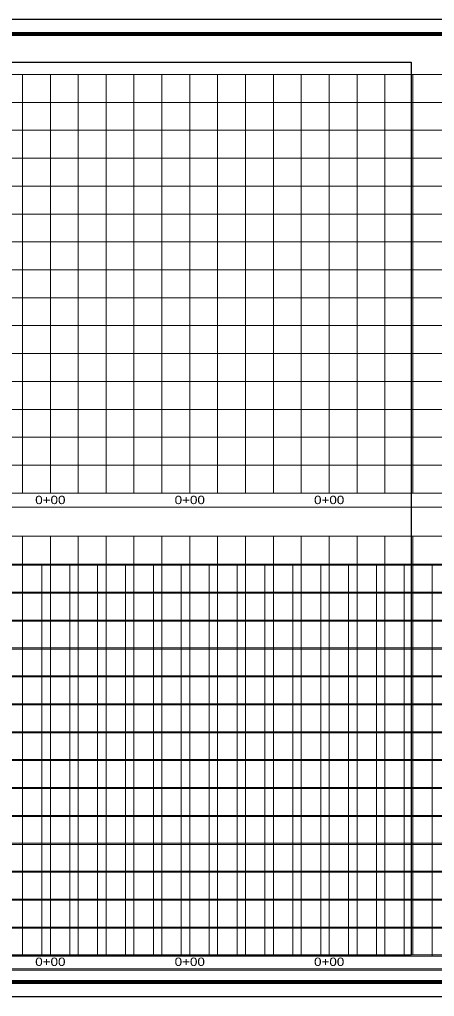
# Model space of a CAD drawing. Extents: x 2246932 to 2264252, y 7095151 to 7098651.
# Drawn here: x 2248981 to 2250469, y 7095151 to 7098651 of the extents above; entities that cross this region are included whole.
import ezdxf
from ezdxf.enums import TextEntityAlignment as Align

# ---------------------------------------------------------------- set-up
doc = ezdxf.new("R2010")
doc.units = 0
doc.header["$LTSCALE"] = 12
for name, color, linetype, lineweight in [('1', 7, 'Continuous', 80), ('59', 7, 'Continuous', 13), ('62', 7, 'Continuous', 13), ('63', 7, 'Continuous', 25)]:
    doc.layers.add(name, color=color, linetype=linetype, lineweight=lineweight)
doc.layers.add('22', color=7, linetype='Continuous')

msp = doc.modelspace()

# ---------------------------------------------------------------- linework, layer by layer
at = {"layer": '1'}
for p, q in [((2264052.09, 7098598.35), (2247157.09, 7098598.35)), ((2247157.09, 7095203.35), (2264052.09, 7095203.35))]:
    msp.add_line(p, q, dxfattribs=at)
at = {"layer": '1', "lineweight": 25}
msp.add_line((2247104.59, 7095150.85), (2264104.59, 7095150.85), dxfattribs=at)
msp.add_lwpolyline([(2264104.59, 7095150.85), (2264104.59, 7098650.85), (2247104.59, 7098650.85), (2247104.59, 7095150.85)], dxfattribs=at)
at = {"layer": '59'}
for p, q in [((2247310.97, 7096695.64), (2262610.97, 7096695.64)), ((2249060.97, 7095295.64), (2249060.97, 7096695.64)), ((2249160.97, 7095295.64), (2249160.97, 7096695.64)), ((2249260.97, 7095295.64), (2249260.97, 7096695.64)), ((2249360.97, 7095295.64), (2249360.97, 7096695.64)), ((2249460.97, 7096695.64), (2249460.97, 7095295.64)), ((2249560.97, 7095295.64), (2249560.97, 7096695.64)), ((2249660.97, 7095295.64), (2249660.97, 7096695.64)), ((2249760.97, 7095295.64), (2249760.97, 7096695.64)), ((2249860.97, 7095295.64), (2249860.97, 7096695.64)), ((2249960.97, 7096695.64), (2249960.97, 7095295.64)), ((2250060.97, 7095295.64), (2250060.97, 7096695.64)), ((2250160.97, 7095295.64), (2250160.97, 7096695.64)), ((2250260.97, 7095295.64), (2250260.97, 7096695.64)), ((2250360.97, 7095295.64), (2250360.97, 7096695.64)), ((2250460.97, 7096695.64), (2250460.97, 7095295.64)), ((2262610.97, 7095295.64), (2247310.97, 7095295.64)), ((2262610.97, 7095245.64), (2247310.97, 7095245.64))]:
    msp.add_line(p, q, dxfattribs=at)
for points in [[(2247460.97, 7096595.64), (2262460.97, 7096595.64), (2262610.97, 7096595.64)], [(2247460.97, 7096495.64), (2262460.97, 7096495.64), (2262610.97, 7096495.64)], [(2247460.97, 7096395.64), (2262460.97, 7096395.64), (2262610.97, 7096395.64)], [(2247460.97, 7096295.64), (2262460.97, 7096295.64), (2262610.97, 7096295.64)], [(2247460.97, 7096195.64), (2262460.97, 7096195.64), (2262610.97, 7096195.64)], [(2247454.92, 7096095.64), (2262460.97, 7096095.64), (2262610.97, 7096095.64)], [(2247460.97, 7095995.64), (2262460.97, 7095995.64), (2262610.97, 7095995.64)], [(2247460.97, 7095895.64), (2262460.97, 7095895.64), (2262610.97, 7095895.64)], [(2247460.97, 7095795.64), (2262460.97, 7095795.64), (2262610.97, 7095795.64)], [(2247460.97, 7095695.64), (2262460.97, 7095695.64), (2262610.97, 7095695.64)], [(2247460.97, 7095595.64), (2262460.97, 7095595.64), (2262610.97, 7095595.64)], [(2247460.97, 7095495.64), (2262460.97, 7095495.64), (2262610.97, 7095495.64)], [(2247460.97, 7095395.64), (2262460.97, 7095395.64), (2262610.97, 7095395.64)]]:
    msp.add_lwpolyline(points, dxfattribs=at)
at = {"layer": '62'}
for p, q in [((2247941.45, 7098454.14), (2263241.45, 7098454.14)), ((2248991.45, 7098454.14), (2248991.45, 7096954.14)), ((2249091.45, 7098454.14), (2249091.45, 7096954.14)), ((2249191.45, 7098454.14), (2249191.45, 7096954.14)), ((2249291.45, 7098454.14), (2249291.45, 7096954.14)), ((2249391.45, 7098454.14), (2249391.45, 7096954.14)), ((2249491.45, 7098454.14), (2249491.45, 7096954.14)), ((2249591.45, 7098454.14), (2249591.45, 7096954.14)), ((2249691.45, 7098454.14), (2249691.45, 7096954.14)), ((2249791.45, 7098454.14), (2249791.45, 7096954.14)), ((2249891.45, 7098454.14), (2249891.45, 7096954.14)), ((2249991.45, 7098454.14), (2249991.45, 7096954.14)), ((2250091.45, 7098454.14), (2250091.45, 7096954.14)), ((2250191.45, 7098454.14), (2250191.45, 7096954.14)), ((2250291.45, 7098454.14), (2250291.45, 7096954.14)), ((2250391.45, 7098454.14), (2250391.45, 7096954.14)), ((2259241.45, 7097654.14), (2249441.45, 7097654.14)), ((2263241.45, 7096954.14), (2247941.45, 7096954.14)), ((2263241.45, 7096904.14), (2247941.45, 7096904.14)), ((2247941.45, 7096799.51), (2263241.45, 7096799.51)), ((2248991.45, 7096799.51), (2248991.45, 7095299.51)), ((2249091.45, 7096799.51), (2249091.45, 7095299.51)), ((2249191.45, 7096799.51), (2249191.45, 7095299.51)), ((2249291.45, 7096799.51), (2249291.45, 7095299.51)), ((2249391.45, 7096799.51), (2249391.45, 7095299.51)), ((2249491.45, 7096799.51), (2249491.45, 7095299.51)), ((2249591.45, 7096799.51), (2249591.45, 7095299.51)), ((2249691.45, 7096799.51), (2249691.45, 7095299.51)), ((2249791.45, 7096799.51), (2249791.45, 7095299.51)), ((2249891.45, 7096799.51), (2249891.45, 7095299.51)), ((2249991.45, 7096799.51), (2249991.45, 7095299.51)), ((2250091.45, 7096799.51), (2250091.45, 7095299.51)), ((2250191.45, 7096799.51), (2250191.45, 7095299.51)), ((2250291.45, 7096799.51), (2250291.45, 7095299.51)), ((2250391.45, 7096799.51), (2250391.45, 7095299.51)), ((2259241.45, 7095999.51), (2249441.45, 7095999.51)), ((2263241.45, 7095299.51), (2247941.45, 7095299.51)), ((2263241.45, 7095249.51), (2247941.45, 7095249.51))]:
    msp.add_line(p, q, dxfattribs=at)
for points in [[(2248091.45, 7098354.14), (2263091.45, 7098354.14), (2263241.45, 7098354.14)], [(2248091.45, 7098254.14), (2263091.45, 7098254.14), (2263241.45, 7098254.14)], [(2248091.45, 7098154.14), (2263091.45, 7098154.14), (2263241.45, 7098154.14)], [(2248091.45, 7098054.14), (2263091.45, 7098054.14), (2263241.45, 7098054.14)], [(2248091.45, 7097954.14), (2263091.45, 7097954.14), (2263241.45, 7097954.14)], [(2248091.45, 7097854.14), (2263091.45, 7097854.14), (2263241.45, 7097854.14)], [(2248091.45, 7097754.14), (2263091.45, 7097754.14), (2263241.45, 7097754.14)], [(2248091.45, 7097654.14), (2263091.45, 7097654.14), (2263241.45, 7097654.14)], [(2248091.45, 7097554.14), (2263091.45, 7097554.14), (2263241.45, 7097554.14)], [(2248091.45, 7097454.14), (2263091.45, 7097454.14), (2263241.45, 7097454.14)], [(2248091.45, 7097354.14), (2263091.45, 7097354.14), (2263241.45, 7097354.14)], [(2248091.45, 7097254.14), (2263091.45, 7097254.14), (2263241.45, 7097254.14)], [(2248091.45, 7097154.14), (2263091.45, 7097154.14), (2263241.45, 7097154.14)], [(2248091.45, 7097054.14), (2263091.45, 7097054.14), (2263241.45, 7097054.14)], [(2248091.45, 7096699.51), (2263091.45, 7096699.51), (2263241.45, 7096699.51)], [(2248091.45, 7096599.51), (2263091.45, 7096599.51), (2263241.45, 7096599.51)], [(2248091.45, 7096499.51), (2263091.45, 7096499.51), (2263241.45, 7096499.51)], [(2248091.45, 7096399.51), (2263091.45, 7096399.51), (2263241.45, 7096399.51)], [(2248091.45, 7096299.51), (2263091.45, 7096299.51), (2263241.45, 7096299.51)], [(2248091.45, 7096199.51), (2263091.45, 7096199.51), (2263241.45, 7096199.51)], [(2248091.45, 7096099.51), (2263091.45, 7096099.51), (2263241.45, 7096099.51)], [(2248091.45, 7095999.51), (2263091.45, 7095999.51), (2263241.45, 7095999.51)], [(2248091.45, 7095899.51), (2263091.45, 7095899.51), (2263241.45, 7095899.51)], [(2248091.45, 7095799.51), (2263091.45, 7095799.51), (2263241.45, 7095799.51)], [(2248091.45, 7095699.51), (2263091.45, 7095699.51), (2263241.45, 7095699.51)], [(2248091.45, 7095599.51), (2263091.45, 7095599.51), (2263241.45, 7095599.51)], [(2248091.45, 7095499.51), (2263091.45, 7095499.51), (2263241.45, 7095499.51)], [(2248091.45, 7095399.51), (2263091.45, 7095399.51), (2263241.45, 7095399.51)]]:
    msp.add_lwpolyline(points, dxfattribs=at)
at = {"layer": '63'}
msp.add_lwpolyline([(2250385.73, 7095298.54), (2248683.57, 7095298.54), (2248683.57, 7098498.04), (2250385.73, 7098498.04)], close=True, dxfattribs=at)

# ---------------------------------------------------------------- texts
at = {"layer": '22', "width": 1.2}
for p in [(2249091.45, 7096914.74), (2249591.45, 7096914.74), (2250091.45, 7096914.74), (2249091.45, 7095260.11), (2249591.45, 7095260.11), (2250091.45, 7095260.11)]:
    msp.add_text('0+00', height=30, dxfattribs=at).set_placement(p, align=Align.CENTER)

doc.saveas('drawing.dxf')
